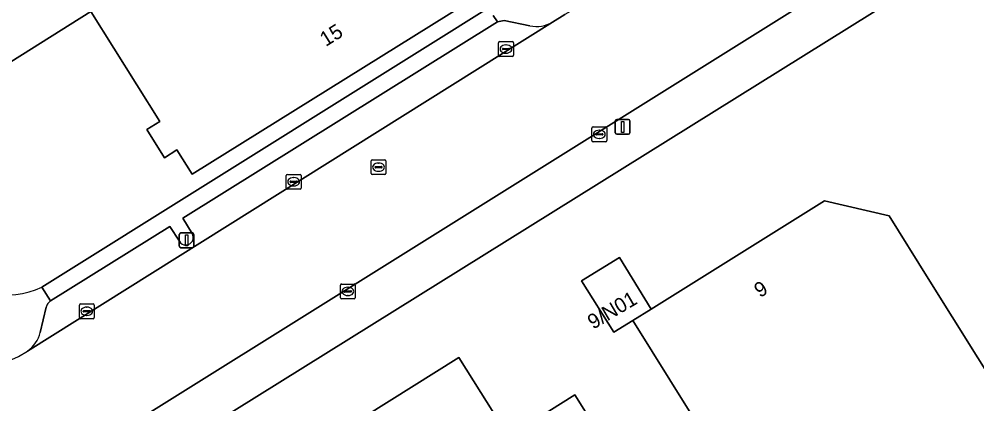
# Model space of a CAD drawing. Extents: x 158455 to 159797, y 387218 to 388672.
# Drawn here: x 158798.5 to 158863.3, y 387630.6 to 387656.7 of the extents above; entities that cross this region are included whole.
import ezdxf

# ---------------------------------------------------------------- set-up
doc = ezdxf.new("R2010")
doc.units = 0
for name, color, linetype in [('IMGEO_Erf', 7, 'Continuous'), ('IMGEO_Kolk', 7, 'Continuous'), ('IMGEO_Lichtmast', 7, 'Continuous'), ('IMGEO_Pand', 7, 'Continuous'), ('IMGEO_Pand_nummerreeks', 7, 'Continuous'), ('IMGEO_Parkeervlak_open', 7, 'Continuous'), ('IMGEO_Rijbaan_lokaal_gesloten', 7, 'Continuous'), ('IMGEO_Rioolput', 7, 'Continuous'), ('IMGEO_Voetpad_open', 7, 'Continuous')]:
    doc.layers.add(name, color=color, linetype=linetype)

msp = doc.modelspace()

# ---------------------------------------------------------------- linework, layer by layer
at = {"layer": 'IMGEO_Erf'}
for points in [[(158764.769, 387774.917), (158768.349, 387769.194), (158780.329, 387750), (158782.862, 387745.942), (158784.116, 387746.734), (158785.675, 387744.21), (158784.42, 387743.427), (158785.295, 387742.04), (158786.63, 387742.874), (158829.899, 387673.716), (158825.367, 387670.895), (158832.215, 387659.892), (158810.231, 387646.159), (158809.189, 387647.807), (158808.342, 387647.281), (158807.16, 387649.189), (158808.044, 387649.737), (158803.356, 387657.183), (158792.508, 387650.366), (158749.261, 387719.529)], [(158889.005, 387677.476), (158884.006, 387674.377), (158883.615, 387674.152), (158859.384, 387659.046), (158794.528, 387618.614), (158789.575, 387615.526), (158787.01, 387619.309), (158783.472, 387624.969), (158781.948, 387627.373), (158778.071, 387633.488), (158774.808, 387638.724), (158774.068, 387639.841), (158771.484, 387643.741), (158770.998, 387644.552), (158768.064, 387649.308), (158764.23, 387655.435), (158760.938, 387660.621)], [(158800.056, 387638.516), (158834.012, 387659.773)], [(158872.376, 387578.837), (158859.303, 387600.001), (158861.74, 387601.499), (158840.043, 387636.272), (158838.764, 387635.468), (158836.586, 387638.954), (158839.138, 387640.534), (158841.287, 387637.037), (158853.016, 387644.366), (158857.397, 387643.355), (158860.048, 387639.116), (158870.011, 387623.182)], [(158814.132, 387624.896), (158828.272, 387633.764), (158831.63, 387628.41), (158836.129, 387631.232), (158838.785, 387626.997)]]:
    msp.add_lwpolyline(points, dxfattribs=at)
msp.add_arc((158797.718, 387643.523), 5.526, 219.8472, 295.03619, dxfattribs=at)
at = {"layer": 'IMGEO_Kolk'}
for p, q in [((158830.962, 387654.214), (158830.962, 387655.066)), ((158831.037, 387655.14), (158831.889, 387655.14)), ((158831.264, 387654.683), (158831.662, 387654.683)), ((158831.45, 387654.92), (158831.475, 387654.92)), ((158831.963, 387655.066), (158831.963, 387654.214)), ((158831.889, 387654.14), (158831.037, 387654.14)), ((158831.221, 387654.634), (158831.221, 387654.646)), ((158831.659, 387654.597), (158831.261, 387654.597)), ((158831.473, 387654.36), (158831.448, 387654.36)), ((158831.705, 387654.646), (158831.705, 387654.634)), ((158837.284, 387648.439), (158837.284, 387649.291)), ((158837.359, 387649.365), (158838.211, 387649.365)), ((158837.543, 387648.859), (158837.543, 387648.871)), ((158837.586, 387648.908), (158837.984, 387648.908)), ((158837.772, 387649.145), (158837.797, 387649.145)), ((158838.027, 387648.871), (158838.027, 387648.859)), ((158838.285, 387649.291), (158838.285, 387648.439)), ((158838.211, 387648.365), (158837.359, 387648.365)), ((158837.981, 387648.822), (158837.583, 387648.822)), ((158837.795, 387648.585), (158837.77, 387648.585)), ((158816.596, 387645.23), (158816.596, 387646.082)), ((158816.671, 387646.156), (158817.523, 387646.156)), ((158816.855, 387645.65), (158816.855, 387645.662)), ((158817.293, 387645.613), (158816.895, 387645.613)), ((158816.898, 387645.699), (158817.296, 387645.699)), ((158817.084, 387645.936), (158817.109, 387645.936)), ((158817.339, 387645.662), (158817.339, 387645.65)), ((158817.597, 387646.082), (158817.597, 387645.23)), ((158817.523, 387645.156), (158816.671, 387645.156)), ((158817.107, 387645.376), (158817.082, 387645.376)), ((158820.261, 387637.807), (158820.261, 387638.659)), ((158820.336, 387638.733), (158821.188, 387638.733)), ((158820.749, 387638.513), (158820.774, 387638.513)), ((158821.262, 387638.659), (158821.262, 387637.807)), ((158820.52, 387638.227), (158820.52, 387638.239)), ((158820.958, 387638.19), (158820.56, 387638.19)), ((158820.563, 387638.276), (158820.961, 387638.276)), ((158820.772, 387637.953), (158820.747, 387637.953)), ((158821.004, 387638.239), (158821.004, 387638.227)), ((158802.59, 387636.459), (158802.59, 387637.311)), ((158802.665, 387637.385), (158803.517, 387637.385)), ((158803.078, 387637.165), (158803.103, 387637.165)), ((158803.591, 387637.311), (158803.591, 387636.459)), ((158821.188, 387637.733), (158820.336, 387637.733)), ((158802.849, 387636.879), (158802.849, 387636.891)), ((158803.287, 387636.842), (158802.889, 387636.842)), ((158802.892, 387636.928), (158803.29, 387636.928)), ((158803.101, 387636.605), (158803.076, 387636.605)), ((158803.333, 387636.891), (158803.333, 387636.879)), ((158803.517, 387636.385), (158802.665, 387636.385))]:
    msp.add_line(p, q, dxfattribs=at)
for points in [[(158830.962, 387654.214), (158830.962, 387655.066)], [(158831.037, 387655.14), (158831.889, 387655.14)], [(158831.963, 387655.066), (158831.963, 387654.214)], [(158831.889, 387654.14), (158831.037, 387654.14)], [(158837.284, 387648.439), (158837.284, 387649.291)], [(158837.359, 387649.365), (158838.211, 387649.365)], [(158838.285, 387649.291), (158838.285, 387648.439)], [(158838.211, 387648.365), (158837.359, 387648.365)], [(158816.596, 387645.23), (158816.596, 387646.082)], [(158816.671, 387646.156), (158817.523, 387646.156)], [(158817.597, 387646.082), (158817.597, 387645.23)], [(158817.523, 387645.156), (158816.671, 387645.156)], [(158820.261, 387637.807), (158820.261, 387638.659)], [(158820.336, 387638.733), (158821.188, 387638.733)], [(158821.262, 387638.659), (158821.262, 387637.807)], [(158802.59, 387636.459), (158802.59, 387637.311)], [(158802.665, 387637.385), (158803.517, 387637.385)], [(158803.591, 387637.311), (158803.591, 387636.459)], [(158821.188, 387637.733), (158820.336, 387637.733)], [(158803.517, 387636.385), (158802.665, 387636.385)]]:
    msp.add_lwpolyline(points, dxfattribs=at)
for centre, radius, start, end in [((158831.039, 387655.064), 0.0765, 91.55205, 178.44795), ((158831.039, 387655.064), 0.0765, 91.55205, 178.44795), ((158831.261, 387654.643), 0.0403, 85.87752, 175.75265), ((158831.666, 387654.645), 0.0386, 1.73085, 96.63898), ((158831.887, 387655.064), 0.0765, 1.55205, 88.44795), ((158831.887, 387655.064), 0.0765, 1.55205, 88.44795), ((158831.039, 387654.216), 0.0765, 181.55205, 268.44795), ((158831.039, 387654.216), 0.0765, 181.55205, 268.44795), ((158831.258, 387654.633), 0.0366, 178.93798, 274.71019), ((158831.662, 387654.64), 0.043, 264.86636, 352.45326), ((158831.887, 387654.216), 0.0765, 271.55205, 358.44795), ((158831.887, 387654.216), 0.0765, 271.55205, 358.44795), ((158837.361, 387649.289), 0.0765, 91.55205, 178.44795), ((158837.361, 387649.289), 0.0765, 91.55205, 178.44795), ((158837.583, 387648.868), 0.0403, 85.87752, 175.75265), ((158837.58, 387648.858), 0.0366, 178.93798, 274.71019), ((158837.984, 387648.865), 0.043, 264.86636, 352.45326), ((158837.988, 387648.87), 0.0386, 1.73085, 96.63898), ((158838.209, 387649.289), 0.0765, 1.55205, 88.44795), ((158838.209, 387649.289), 0.0765, 1.55205, 88.44795), ((158837.361, 387648.441), 0.0765, 181.55205, 268.44795), ((158837.361, 387648.441), 0.0765, 181.55205, 268.44795), ((158838.209, 387648.441), 0.0765, 271.55205, 358.44795), ((158838.209, 387648.441), 0.0765, 271.55205, 358.44795), ((158816.673, 387646.08), 0.0765, 91.55205, 178.44795), ((158816.673, 387646.08), 0.0765, 91.55205, 178.44795), ((158816.895, 387645.659), 0.0403, 85.87752, 175.75265), ((158816.892, 387645.649), 0.0366, 178.93798, 274.71019), ((158817.296, 387645.656), 0.043, 264.86636, 352.45326), ((158817.3, 387645.661), 0.0386, 1.73085, 96.63898), ((158817.521, 387646.08), 0.0765, 1.55205, 88.44795), ((158817.521, 387646.08), 0.0765, 1.55205, 88.44795), ((158816.673, 387645.232), 0.0765, 181.55205, 268.44795), ((158816.673, 387645.232), 0.0765, 181.55205, 268.44795), ((158817.521, 387645.232), 0.0765, 271.55205, 358.44795), ((158817.521, 387645.232), 0.0765, 271.55205, 358.44795), ((158820.338, 387638.657), 0.0765, 91.55205, 178.44795), ((158820.338, 387638.657), 0.0765, 91.55205, 178.44795), ((158821.186, 387638.657), 0.0765, 1.55205, 88.44795), ((158821.186, 387638.657), 0.0765, 1.55205, 88.44795), ((158820.56, 387638.236), 0.0403, 85.87752, 175.75265), ((158820.557, 387638.226), 0.0366, 178.93798, 274.71019), ((158820.961, 387638.233), 0.043, 264.86636, 352.45326), ((158820.965, 387638.238), 0.0386, 1.73085, 96.63898), ((158802.667, 387637.309), 0.0765, 91.55205, 178.44795), ((158802.667, 387637.309), 0.0765, 91.55205, 178.44795), ((158803.515, 387637.309), 0.0765, 1.55205, 88.44795), ((158803.515, 387637.309), 0.0765, 1.55205, 88.44795), ((158820.338, 387637.809), 0.0765, 181.55205, 268.44795), ((158820.338, 387637.809), 0.0765, 181.55205, 268.44795), ((158821.186, 387637.809), 0.0765, 271.55205, 358.44795), ((158821.186, 387637.809), 0.0765, 271.55205, 358.44795), ((158802.889, 387636.888), 0.0403, 85.87752, 175.75265), ((158802.886, 387636.878), 0.0366, 178.93798, 274.71019), ((158803.29, 387636.885), 0.043, 264.86636, 352.45326), ((158803.294, 387636.89), 0.0386, 1.73085, 96.63898), ((158802.667, 387636.461), 0.0765, 181.55205, 268.44795), ((158802.667, 387636.461), 0.0765, 181.55205, 268.44795), ((158803.515, 387636.461), 0.0765, 271.55205, 358.44795), ((158803.515, 387636.461), 0.0765, 271.55205, 358.44795)]:
    msp.add_arc(centre, radius, start, end, dxfattribs=at)
for centre, major_axis, ratio, start_param, end_param in [((158831.449, 387654.64), (-0.387, 0.002), 0.722429, 4.712389, 7.853982), ((158831.474, 387654.64), (-0.39, 0.002), 0.717154, 1.570796, 4.712389), ((158837.771, 387648.865), (-0.387, 0.002), 0.722429, 4.712389, 7.853982), ((158837.796, 387648.865), (-0.39, 0.002), 0.717154, 1.570796, 4.712389), ((158817.083, 387645.656), (-0.387, 0.002), 0.722429, 4.712389, 7.853982), ((158817.108, 387645.656), (-0.39, 0.002), 0.717154, 1.570796, 4.712389), ((158820.748, 387638.233), (-0.387, 0.002), 0.722429, 4.712389, 7.853982), ((158820.773, 387638.233), (-0.39, 0.002), 0.717154, 1.570796, 4.712389), ((158803.077, 387636.885), (-0.387, 0.002), 0.722429, 4.712389, 7.853982), ((158803.102, 387636.885), (-0.39, 0.002), 0.717154, 1.570796, 4.712389)]:
    msp.add_ellipse(centre, major_axis=major_axis, ratio=ratio, start_param=start_param, end_param=end_param, dxfattribs=at)
at = {"layer": 'IMGEO_Lichtmast'}
for p, q in [((158838.864, 387648.969), (158838.864, 387649.769)), ((158838.864, 387649.769), (158838.864, 387648.969)), ((158838.964, 387649.869), (158839.754, 387649.869)), ((158839.754, 387649.869), (158838.964, 387649.869)), ((158839.854, 387649.769), (158839.854, 387648.969)), ((158839.854, 387648.969), (158839.854, 387649.769)), ((158839.754, 387648.869), (158838.964, 387648.869)), ((158838.964, 387648.869), (158839.754, 387648.869)), ((158809.35, 387641.291), (158809.35, 387642.091)), ((158809.35, 387642.091), (158809.35, 387641.291)), ((158809.45, 387642.191), (158810.24, 387642.191)), ((158810.24, 387642.191), (158809.45, 387642.191)), ((158810.34, 387642.091), (158810.34, 387641.291)), ((158810.34, 387641.291), (158810.34, 387642.091)), ((158810.24, 387641.191), (158809.45, 387641.191)), ((158809.45, 387641.191), (158810.24, 387641.191))]:
    msp.add_line(p, q, dxfattribs=at)
for points in [[(158839.284, 387649.744), (158839.434, 387649.744), (158839.434, 387648.994), (158839.284, 387648.994), (158839.284, 387649.744)], [(158809.77, 387642.066), (158809.92, 387642.066), (158809.92, 387641.316), (158809.77, 387641.316), (158809.77, 387642.066)]]:
    msp.add_lwpolyline(points, dxfattribs=at)
for centre, start, end in [((158838.964, 387649.769), 90, 180), ((158838.964, 387649.769), 90, 180), ((158839.754, 387649.769), 0, 90), ((158839.754, 387649.769), 360, 90), ((158838.964, 387648.969), 180, 270), ((158838.964, 387648.969), 180, 270), ((158839.754, 387648.969), 270, 0), ((158839.754, 387648.969), 270, 0), ((158809.45, 387642.091), 90, 180), ((158809.45, 387642.091), 90, 180), ((158810.24, 387642.091), 0, 90), ((158810.24, 387642.091), 360, 90), ((158809.45, 387641.291), 180, 270), ((158809.45, 387641.291), 180, 270), ((158810.24, 387641.291), 270, 0), ((158810.24, 387641.291), 270, 0)]:
    msp.add_arc(centre, 0.1, start, end, dxfattribs=at)
at = {"layer": 'IMGEO_Pand'}
for points in [[(158785.295, 387742.04), (158767.085, 387730.664), (158749.261, 387719.529), (158792.508, 387650.366), (158803.356, 387657.183), (158808.044, 387649.737), (158807.16, 387649.189), (158808.342, 387647.281), (158809.189, 387647.807), (158810.231, 387646.159), (158832.215, 387659.892), (158825.367, 387670.895), (158829.899, 387673.716), (158786.63, 387742.874)], [(158841.287, 387637.037), (158840.043, 387636.272), (158861.74, 387601.499), (158881.216, 387613.661), (158873.828, 387625.553), (158870.011, 387623.182), (158860.048, 387639.116), (158857.397, 387643.355), (158853.016, 387644.366)], [(158841.287, 387637.037), (158839.138, 387640.534), (158836.586, 387638.954), (158838.764, 387635.468), (158840.043, 387636.272)], [(158838.785, 387626.997), (158836.129, 387631.232), (158831.63, 387628.41), (158828.272, 387633.764), (158814.132, 387624.896), (158821.999, 387612.145), (158831.934, 387596.259), (158837.806, 387586.563), (158856.748, 387598.356), (158850.687, 387608.02)]]:
    msp.add_lwpolyline(points, close=True, dxfattribs=at)
at = {"layer": 'IMGEO_Parkeervlak_open'}
for points in [[(158799.078, 387634.195), (158834.62, 387656.451)], [(158833.086, 387656.219), (158831.35, 387656.565), (158830.883, 387656.48), (158809.601, 387643.18), (158810.221, 387642.151)], [(158809.357, 387641.623), (158808.719, 387642.629), (158800.645, 387637.583)], [(158800.35, 387637.168), (158799.945, 387635.453)]]:
    msp.add_lwpolyline(points, dxfattribs=at)
for centre, radius, start, end in [((158833.543, 387658.382), 2.211, 258.05668, 299.14363), ((158809.792, 387641.883), 0.506, 210.869, 31.99013), ((158800.906, 387637.085), 0.562, 117.68106, 171.5052), ((158797.93, 387635.914), 2.067, 303.73973, 347.11188)]:
    msp.add_arc(centre, radius, start, end, dxfattribs=at)
at = {"layer": 'IMGEO_Rijbaan_lokaal_gesloten'}
for points in [[(158945.416, 387725.594), (158927.362, 387714.425), (158920.835, 387710.34), (158895.883, 387694.779), (158890.625, 387691.491), (158885.188, 387688.104), (158880.72, 387685.337), (158880.072, 387684.887), (158858.962, 387671.706), (158855.957, 387669.782), (158835.817, 387657.182), (158835.446, 387656.987), (158834.62, 387656.451), (158799.078, 387634.195)], [(158789.305, 387636.07), (158782.556, 387631.666), (158790.258, 387619.355), (158883.627, 387677.735), (158887.243, 387680.019), (158907.509, 387692.653)]]:
    msp.add_lwpolyline(points, dxfattribs=at)
msp.add_arc((158795.139, 387640.072), 7.075, 214.45059, 303.82838, dxfattribs=at)
at = {"layer": 'IMGEO_Rioolput'}
for p, q in [((158822.338, 387646.214), (158822.338, 387647.066)), ((158822.413, 387647.14), (158823.265, 387647.14)), ((158822.826, 387646.92), (158822.851, 387646.92)), ((158823.339, 387647.066), (158823.339, 387646.214)), ((158822.597, 387646.634), (158822.597, 387646.646)), ((158823.035, 387646.597), (158822.637, 387646.597)), ((158822.64, 387646.683), (158823.038, 387646.683)), ((158822.849, 387646.36), (158822.824, 387646.36)), ((158823.081, 387646.646), (158823.081, 387646.634)), ((158823.265, 387646.14), (158822.413, 387646.14))]:
    msp.add_line(p, q, dxfattribs=at)
for points in [[(158822.338, 387646.214), (158822.338, 387647.066)], [(158822.413, 387647.14), (158823.265, 387647.14)], [(158823.339, 387647.066), (158823.339, 387646.214)], [(158823.265, 387646.14), (158822.413, 387646.14)]]:
    msp.add_lwpolyline(points, dxfattribs=at)
for centre, radius, start, end in [((158822.415, 387647.064), 0.0765, 91.55205, 178.44795), ((158822.415, 387647.064), 0.0765, 91.55205, 178.44795), ((158823.263, 387647.064), 0.0765, 1.55205, 88.44795), ((158823.263, 387647.064), 0.0765, 1.55205, 88.44795), ((158822.637, 387646.643), 0.0403, 85.87752, 175.75265), ((158822.634, 387646.633), 0.0366, 178.93798, 274.71019), ((158823.038, 387646.64), 0.043, 264.86636, 352.45326), ((158823.042, 387646.645), 0.0386, 1.73085, 96.63898), ((158822.415, 387646.216), 0.0765, 181.55205, 268.44795), ((158822.415, 387646.216), 0.0765, 181.55205, 268.44795), ((158823.263, 387646.216), 0.0765, 271.55205, 358.44795), ((158823.263, 387646.216), 0.0765, 271.55205, 358.44795)]:
    msp.add_arc(centre, radius, start, end, dxfattribs=at)
for centre, major_axis, ratio, start_param, end_param in [((158822.825, 387646.64), (-0.387, 0.002), 0.722429, 4.712389, 7.853982), ((158822.85, 387646.64), (-0.39, 0.002), 0.717154, 1.570796, 4.712389)]:
    msp.add_ellipse(centre, major_axis=major_axis, ratio=ratio, start_param=start_param, end_param=end_param, dxfattribs=at)
at = {"layer": 'IMGEO_Voetpad_open'}
for points in [[(158883.627, 387677.735), (158790.258, 387619.355), (158788.589, 387618.312), (158787.69, 387619.674), (158787.01, 387619.309), (158789.575, 387615.526), (158794.528, 387618.614), (158859.384, 387659.046), (158883.615, 387674.152), (158883.066, 387674.978)], [(158834.012, 387659.773), (158800.056, 387638.516), (158800.645, 387637.583), (158808.719, 387642.629), (158809.357, 387641.623)], [(158810.221, 387642.151), (158809.601, 387643.18), (158830.883, 387656.48), (158830.598, 387656.914)], [(158830.598, 387656.914), (158830.883, 387656.48), (158831.35, 387656.565), (158833.086, 387656.219)], [(158834.62, 387656.451), (158835.446, 387656.987)], [(158800.645, 387637.583), (158800.056, 387638.516)], [(158799.945, 387635.453), (158800.35, 387637.168)]]:
    msp.add_lwpolyline(points, dxfattribs=at)
for centre, radius, start, end in [((158833.543, 387658.382), 2.211, 258.05668, 299.14363), ((158809.792, 387641.883), 0.506, 210.869, 31.99013), ((158797.718, 387643.523), 5.526, 219.8472, 295.03619), ((158800.906, 387637.085), 0.562, 117.68106, 171.5052), ((158795.139, 387640.072), 7.075, 214.45059, 303.82838), ((158797.93, 387635.914), 2.067, 303.73973, 347.11188)]:
    msp.add_arc(centre, radius, start, end, dxfattribs=at)

# ---------------------------------------------------------------- texts
at = {"layer": 'IMGEO_Pand_nummerreeks'}
for s, rotation, p in [('15', 31.99226, (158819.265, 387654.773)), ('9', 31.99968, (158848.656, 387637.774)), ('9/N01', 30.39873, (158837.36, 387635.636))]:
    msp.add_text(s, height=1, rotation=rotation, dxfattribs=at).set_placement(p)

doc.saveas('drawing.dxf')
